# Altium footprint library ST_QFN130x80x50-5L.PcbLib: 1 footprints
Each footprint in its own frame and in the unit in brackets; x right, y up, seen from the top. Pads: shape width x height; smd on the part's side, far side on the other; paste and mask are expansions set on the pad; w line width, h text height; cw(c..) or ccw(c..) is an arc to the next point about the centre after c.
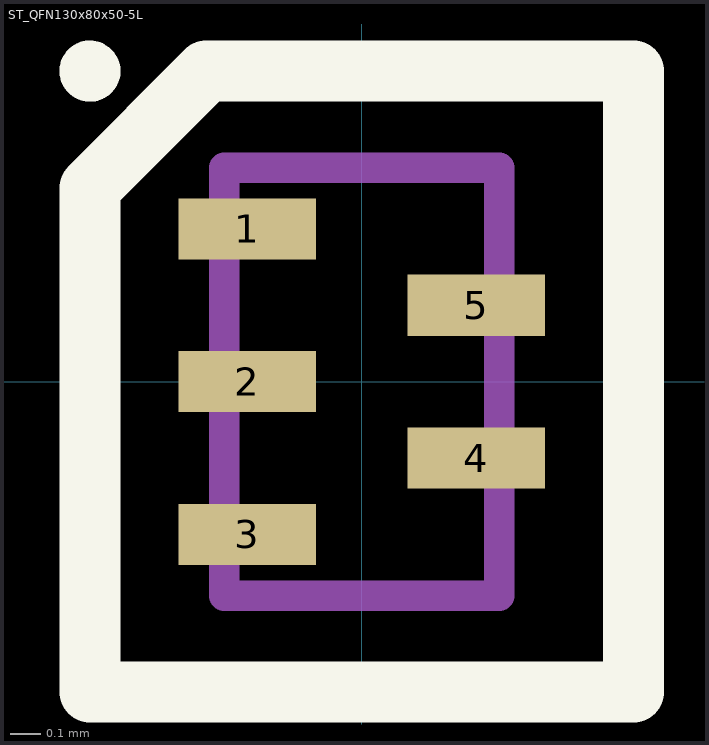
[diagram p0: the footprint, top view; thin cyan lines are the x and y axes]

## ST_QFN130x80x50-5L [mm] "ST_QFN130x80x50-5L"
height 0.4
pads (5):
  rect 0.45x0.2 smd mask+0.05: 1(-0.375,0.5) 2(-0.375,0) 3(-0.375,-0.5) 4(0.375,-0.25) 5(0.375,0.25)
Top Overlay:
  circle w0.1: c-0.889,1.016 r0.05
  lines w0.2: -0.889,-1.016 -0.889,0.634 -0.509,1.015 0.889,1.016 0.889,-1.016 -0.889,-1.016
Mechanical 13:
  lines w0.1: -0.45,-0.7 -0.45,0.7 0.45,0.7 0.45,-0.7 -0.45,-0.7
3D body "QFN130x80x50-5L.step": height 0.4, standoff 0, extent -0.451,-0.7 0.451,0.7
